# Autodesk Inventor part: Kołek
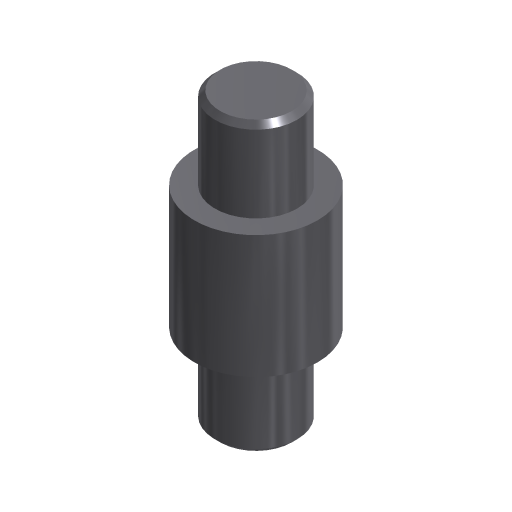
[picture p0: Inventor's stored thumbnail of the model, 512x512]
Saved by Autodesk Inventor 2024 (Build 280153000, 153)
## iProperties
Company: ATC
Shininess: 20.0
Angle Display Precision: 2
Document Length Units: 11269
Document Angle Units: 11279
Document Time Units: 11290
Document Mass Units: 11283
Document Length Units Precision: 3
Document Angle Units Precision: 2
Created: 2023-03
Part Number: Kołek
Material: Kurs-AJ
Document SubType Name: Modelowanie
Designer: Andrzej Jaskulski
Density: 1 g/cm^3
Stock Number: Kołek
Mass: 21.5539 g
Surface Area: 10.6533 cm^2
Volume: 2.15539 cm^3
Appearance: Metal-stal (polerowana)
Checked By: A.J.
Engr Approved By: Andrzej Jaskulski
Mfg Approved By: Andrzej Jaskulski
Authority: A.J.
Density: 0.0
Volumn: 0.0
Area: 0.0
PropertySet Name: Model Information
Control State: 0
Master: False
Checked Out: False
Title: A.J.: Kurs R2024-MEP
Author: Andrzej Jaskulski
Revision Number: 1/24
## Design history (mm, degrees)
node "Początek"
  node "Płaszczyzna YZ"
  node "Płaszczyzna XZ"
  node "Płaszczyzna XY"
  node "Oś X"
  node "Oś Y"
  node "Oś Z"
sketch "Szkic1"
  geometry: C1 r 4 at (41.919, -38.642) reference; C2 r 6 at (41.919, -38.642)
  constraints: 1 centre point, 1 coincident
  dimensions: "d0" = 2 radial gap between concentric circles of C2 C1
extrude "Wyciągnięcie proste1" new body sketch "Szkic1" distance "d1" = 12; taper "d2" = 0 deg
extrude "Wyciągnięcie proste2" join sketch "Szkic1" distance "d3" = 8; taper "d4" = 0 deg
node "Płaszczyzna konstrukcyjna1"
chamfer "Faza1" distance "d6" = 0.5; stored, may be unused: second distance "d7" = 0.5, angle "d9" = 45 deg
mirror "Lustro1"
node "Bryła1"
node "Korpusy bryłowe"
node "Korpusy powierzchniowe"
node "Punkt środkowy"
other parameters: "d5" = -6 (= -0.5 x d1), "d8" = 0
